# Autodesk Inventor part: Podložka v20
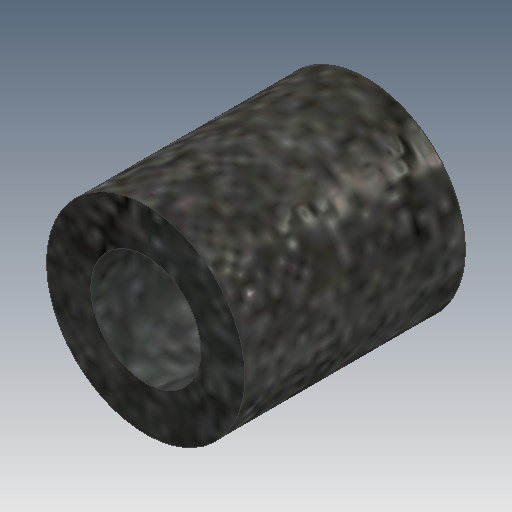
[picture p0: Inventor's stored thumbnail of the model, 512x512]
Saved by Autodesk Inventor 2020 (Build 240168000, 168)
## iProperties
Created: 2025-03
Part Number: Podložka v20
Material: Ocel
Document SubType Name: Modeling
Designer: doma
Density: 7.85 g/cm^3
Appearance: Plech
Mass: 27.6209 g
Surface Area: 21.1115 cm^2
Volume: 3.51858 cm^3
Author: doma
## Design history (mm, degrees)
sketch "Náčrt1"
  geometry: C1 r 5 at (0, 0); C2 r 9 at (0, 0); 1 further point
  constraints: 2 centre point, 2 coincident
  dimensions: "d0" = 10 diameter of C1; "d1" = 18 diameter of C2
extrude "Vysunutí1" new body sketch "Náčrt1" distance "d2" = 20; taper "d3" = 0 deg
node "Těleso1"
